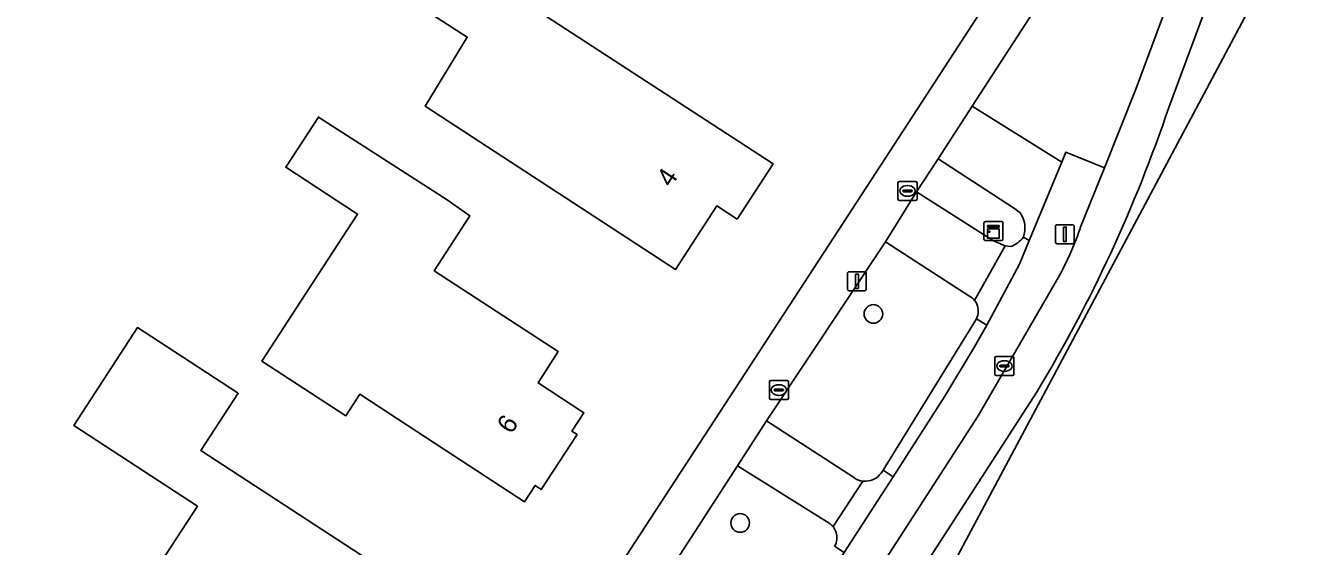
# Model space of a CAD drawing. Extents: x 161139 to 161601, y 381708 to 382245.
# Drawn here: x 161518.7 to 161586, y 382082.4 to 382109.7 of the extents above; entities that cross this region are included whole.
import ezdxf

# ---------------------------------------------------------------- set-up
doc = ezdxf.new("R2010")
doc.units = 0
for name, color, linetype in [('IMGEO_Boom', 7, 'Continuous'), ('IMGEO_Brandkraan', 7, 'Continuous'), ('IMGEO_Erf', 7, 'Continuous'), ('IMGEO_Groenvoorziening', 7, 'Continuous'), ('IMGEO_Kast', 7, 'Continuous'), ('IMGEO_Kolk', 7, 'Continuous'), ('IMGEO_Lichtmast', 7, 'Continuous'), ('IMGEO_Pand', 7, 'Continuous'), ('IMGEO_Pand_nummerreeks', 7, 'Continuous'), ('IMGEO_Parkeervlak_open', 7, 'Continuous'), ('IMGEO_Rijbaan_lokaal_gesloten', 7, 'Continuous'), ('IMGEO_Rijbaan_lokaal_open', 7, 'Continuous'), ('IMGEO_Voetpad_open', 7, 'Continuous')]:
    doc.layers.add(name, color=color, linetype=linetype)

msp = doc.modelspace()

# ---------------------------------------------------------------- linework, layer by layer
at = {"layer": 'IMGEO_Boom'}
for centre in [(161563.196, 382094.579), (161556.197, 382083.607)]:
    msp.add_circle(centre, 0.489, dxfattribs=at)
at = {"layer": 'IMGEO_Brandkraan'}
for p, q in [((161557.732, 382090.159), (161557.732, 382091.011)), ((161557.807, 382091.085), (161558.659, 382091.085)), ((161558.22, 382090.865), (161558.245, 382090.865)), ((161558.733, 382091.011), (161558.733, 382090.159)), ((161557.991, 382090.579), (161557.991, 382090.591)), ((161558.429, 382090.542), (161558.031, 382090.542)), ((161558.034, 382090.628), (161558.432, 382090.628)), ((161558.243, 382090.305), (161558.218, 382090.305)), ((161558.475, 382090.591), (161558.475, 382090.579)), ((161558.659, 382090.085), (161557.807, 382090.085))]:
    msp.add_line(p, q, dxfattribs=at)
for points in [[(161557.732, 382090.159), (161557.732, 382091.011)], [(161557.807, 382091.085), (161558.659, 382091.085)], [(161558.733, 382091.011), (161558.733, 382090.159)], [(161558.659, 382090.085), (161557.807, 382090.085)]]:
    msp.add_lwpolyline(points, dxfattribs=at)
for centre, radius, start, end in [((161557.809, 382091.009), 0.0765, 91.55205, 178.44795), ((161557.809, 382091.009), 0.0765, 91.55205, 178.44795), ((161558.657, 382091.009), 0.0765, 1.55205, 88.44795), ((161558.657, 382091.009), 0.0765, 1.55205, 88.44795), ((161557.809, 382090.161), 0.0765, 181.55205, 268.44795), ((161557.809, 382090.161), 0.0765, 181.55205, 268.44795), ((161558.031, 382090.588), 0.0403, 85.87752, 175.75265), ((161558.028, 382090.578), 0.0366, 178.93798, 274.71019), ((161558.432, 382090.585), 0.043, 264.86636, 352.45326), ((161558.436, 382090.59), 0.0386, 1.73085, 96.63898), ((161558.657, 382090.161), 0.0765, 271.55205, 358.44795), ((161558.657, 382090.161), 0.0765, 271.55205, 358.44795)]:
    msp.add_arc(centre, radius, start, end, dxfattribs=at)
for centre, major_axis, ratio, start_param, end_param in [((161558.219, 382090.585), (-0.387, 0.002), 0.722429, 4.712389, 7.853982), ((161558.244, 382090.585), (-0.39, 0.002), 0.717154, 1.570796, 4.712389)]:
    msp.add_ellipse(centre, major_axis=major_axis, ratio=ratio, start_param=start_param, end_param=end_param, dxfattribs=at)
at = {"layer": 'IMGEO_Erf'}
msp.add_lwpolyline([(161553.295, 382144.911), (161544.61, 382147.101), (161500, 382158.072), (161477.956, 382163.494), (161457.897, 382168.303), (161418.52, 382178.097), (161389.844, 382185.251), (161387.058, 382185.651), (161384.186, 382184.996), (161381.949, 382183.375), (161380.259, 382181.034), (161377.586, 382172.934), (161374.321, 382163.969), (161372.26, 382158.835), (161369.98, 382153.637), (161365.084, 382143.565), (161365.175, 382143.293), (161389.855, 382127.317), (161408.789, 382114.947), (161450.498, 382088.211), (161500, 382056.07), (161523.437, 382040.853), (161561.628, 382099.383), (161581.409, 382129.761)], dxfattribs=at)
for points in [[(161548.616, 382099.647), (161539.661, 382105.481), (161541.863, 382109.109), (161539.49, 382110.634), (161540.764, 382112.614), (161536.361, 382115.445), (161539.948, 382117.916), (161544.995, 382114.67), (161543.277, 382111.999), (161543.522, 382111.842), (161553.735, 382105.188), (161557.924, 382102.459), (161556.035, 382099.56), (161554.976, 382100.25), (161552.805, 382096.917)], [(161534.048, 382104.912), (161540.81, 382100.569), (161542.007, 382099.725), (161540.131, 382096.846), (161545.242, 382093.515), (161546.648, 382092.599), (161545.581, 382090.962), (161547.984, 382089.396), (161547.357, 382088.433), (161547.633, 382088.253), (161545.753, 382085.367), (161545.435, 382085.575), (161544.88, 382084.724), (161540.691, 382087.454), (161536.228, 382090.362), (161535.491, 382089.231), (161531.076, 382092.108), (161534.302, 382097.059), (161536.104, 382099.824), (161532.334, 382102.281)], [(161527.701, 382084.489), (161521.198, 382088.726), (161524.545, 382093.864), (161525.651, 382093.143), (161529.841, 382090.414), (161527.88, 382087.405), (161541.06, 382078.818), (161536.96, 382072.525), (161532.764, 382075.259), (161532.059, 382074.178), (161528.63, 382076.412), (161529.353, 382077.522), (161525.007, 382080.354)]]:
    msp.add_lwpolyline(points, close=True, dxfattribs=at)
at = {"layer": 'IMGEO_Groenvoorziening'}
msp.add_lwpolyline([(161579.832, 382114.053), (161581.47, 382118.537), (161583.268, 382124.041), (161581.267, 382125.334), (161568.38, 382105.476), (161573.086, 382102.543), (161573.302, 382103.064), (161575.329, 382102.253), (161576.98, 382106.377)], close=True, dxfattribs=at)
for points in [[(161566.592, 382102.722), (161565.463, 382100.982), (161569.51, 382098.421), (161570.115, 382098.159), (161570.416, 382098.113)], [(161570.897, 382099.892), (161570.551, 382100.153), (161566.592, 382102.722)], [(161568.212, 382095.532), (161563.831, 382098.367), (161557.579, 382088.971), (161562.195, 382085.975)], [(161563.596, 382086.216), (161563.702, 382086.387), (161568.611, 382094.325)], [(161560.731, 382083.685), (161556.061, 382086.613), (161549.678, 382076.751), (161554.422, 382073.613)], [(161562.648, 382085.805), (161562.819, 382085.798)]]:
    msp.add_lwpolyline(points, dxfattribs=at)
for centre, radius, start, end in [((161569.741, 382099.077), 1.414, 340.48835, 35.17308), ((161569.9, 382099.489), 1.469, 290.54939, 323.02303), ((161567.826, 382094.75), 0.872, 37.93195, 63.73762), ((161567.819, 382094.73), 0.89, 24.7571, 38.63242), ((161567.803, 382094.731), 0.904, 333.32683, 24.31686), ((161562.77, 382086.82), 1.023, 272.73451, 323.82302), ((161562.771, 382086.822), 1.025, 235.774, 263.0862), ((161560.341, 382082.836), 0.935, 38.2235, 65.31507), ((161560.326, 382082.82), 0.956, 17.67097, 38.43487), ((161560.344, 382082.836), 0.935, 330.87903, 17.06204)]:
    msp.add_arc(centre, radius, start, end, dxfattribs=at)
at = {"layer": 'IMGEO_Kast'}
for p, q in [((161569.001, 382098.502), (161569.001, 382099.343)), ((161569.001, 382099.343), (161569.001, 382098.502)), ((161569.076, 382099.427), (161569.917, 382099.427)), ((161569.917, 382099.427), (161569.076, 382099.427)), ((161570.001, 382099.352), (161570.001, 382098.511)), ((161570.001, 382098.511), (161570.001, 382099.352)), ((161569.926, 382098.427), (161569.085, 382098.427)), ((161569.085, 382098.427), (161569.926, 382098.427))]:
    msp.add_line(p, q, dxfattribs=at)
for points in [[(161569.196, 382099.217), (161569.796, 382099.217), (161569.796, 382099.132), (161569.196, 382099.132), (161569.196, 382099.217)], [(161569.196, 382099.042), (161569.796, 382099.042), (161569.796, 382098.553), (161569.196, 382098.553), (161569.196, 382099.042)]]:
    msp.add_lwpolyline(points, dxfattribs=at)
msp.add_circle((161569.28, 382098.891), 0.0377, dxfattribs=at)
for centre, start, end in [((161569.079, 382099.349), 92.4484, 184.28452), ((161569.079, 382099.349), 92.4484, 184.28452), ((161569.923, 382099.349), 2.4484, 94.28452), ((161569.923, 382099.349), 2.4484, 94.28452), ((161569.079, 382098.505), 182.4484, 274.28452), ((161569.079, 382098.505), 182.4484, 274.28452), ((161569.923, 382098.505), 272.4484, 4.28452), ((161569.923, 382098.505), 272.4484, 4.28452)]:
    msp.add_arc(centre, 0.0779, start, end, dxfattribs=at)
at = {"layer": 'IMGEO_Kolk'}
for p, q in [((161564.487, 382100.61), (161564.487, 382101.462)), ((161564.562, 382101.536), (161565.414, 382101.536)), ((161564.746, 382101.03), (161564.746, 382101.042)), ((161565.184, 382100.993), (161564.786, 382100.993)), ((161564.789, 382101.079), (161565.187, 382101.079)), ((161564.975, 382101.316), (161565, 382101.316)), ((161565.23, 382101.042), (161565.23, 382101.03)), ((161565.488, 382101.462), (161565.488, 382100.61)), ((161565.414, 382100.536), (161564.562, 382100.536)), ((161564.998, 382100.756), (161564.973, 382100.756)), ((161569.577, 382091.419), (161569.577, 382092.271)), ((161569.652, 382092.345), (161570.504, 382092.345)), ((161570.578, 382092.271), (161570.578, 382091.419)), ((161569.836, 382091.839), (161569.836, 382091.851)), ((161570.274, 382091.802), (161569.876, 382091.802)), ((161569.879, 382091.888), (161570.277, 382091.888)), ((161570.088, 382091.565), (161570.063, 382091.565)), ((161570.065, 382092.125), (161570.09, 382092.125)), ((161570.32, 382091.851), (161570.32, 382091.839)), ((161570.504, 382091.345), (161569.652, 382091.345))]:
    msp.add_line(p, q, dxfattribs=at)
for points in [[(161564.487, 382100.61), (161564.487, 382101.462)], [(161564.562, 382101.536), (161565.414, 382101.536)], [(161565.488, 382101.462), (161565.488, 382100.61)], [(161565.414, 382100.536), (161564.562, 382100.536)], [(161569.577, 382091.419), (161569.577, 382092.271)], [(161569.652, 382092.345), (161570.504, 382092.345)], [(161570.578, 382092.271), (161570.578, 382091.419)], [(161570.504, 382091.345), (161569.652, 382091.345)]]:
    msp.add_lwpolyline(points, dxfattribs=at)
for centre, radius, start, end in [((161564.564, 382101.46), 0.0765, 91.55205, 178.44795), ((161564.564, 382101.46), 0.0765, 91.55205, 178.44795), ((161564.786, 382101.039), 0.0403, 85.87752, 175.75265), ((161564.783, 382101.029), 0.0366, 178.93798, 274.71019), ((161565.187, 382101.036), 0.043, 264.86636, 352.45326), ((161565.191, 382101.041), 0.0386, 1.73085, 96.63898), ((161565.412, 382101.46), 0.0765, 1.55205, 88.44795), ((161565.412, 382101.46), 0.0765, 1.55205, 88.44795), ((161564.564, 382100.612), 0.0765, 181.55205, 268.44795), ((161564.564, 382100.612), 0.0765, 181.55205, 268.44795), ((161565.412, 382100.612), 0.0765, 271.55205, 358.44795), ((161565.412, 382100.612), 0.0765, 271.55205, 358.44795), ((161569.654, 382092.269), 0.0765, 91.55205, 178.44795), ((161569.654, 382092.269), 0.0765, 91.55205, 178.44795), ((161570.502, 382092.269), 0.0765, 1.55205, 88.44795), ((161570.502, 382092.269), 0.0765, 1.55205, 88.44795), ((161569.876, 382091.848), 0.0403, 85.87752, 175.75265), ((161569.873, 382091.838), 0.0366, 178.93798, 274.71019), ((161570.277, 382091.845), 0.043, 264.86636, 352.45326), ((161570.281, 382091.85), 0.0386, 1.73085, 96.63898), ((161569.654, 382091.421), 0.0765, 181.55205, 268.44795), ((161569.654, 382091.421), 0.0765, 181.55205, 268.44795), ((161570.502, 382091.421), 0.0765, 271.55205, 358.44795), ((161570.502, 382091.421), 0.0765, 271.55205, 358.44795)]:
    msp.add_arc(centre, radius, start, end, dxfattribs=at)
for centre, major_axis, ratio, start_param, end_param in [((161564.974, 382101.036), (-0.387, 0.002), 0.722429, 4.712389, 7.853982), ((161564.999, 382101.036), (-0.39, 0.002), 0.717154, 1.570796, 4.712389), ((161570.064, 382091.845), (-0.387, 0.002), 0.722429, 4.712389, 7.853982), ((161570.089, 382091.845), (-0.39, 0.002), 0.717154, 1.570796, 4.712389)]:
    msp.add_ellipse(centre, major_axis=major_axis, ratio=ratio, start_param=start_param, end_param=end_param, dxfattribs=at)
at = {"layer": 'IMGEO_Lichtmast'}
for p, q in [((161572.752, 382098.361), (161572.752, 382099.161)), ((161572.752, 382099.161), (161572.752, 382098.361)), ((161572.852, 382099.261), (161573.642, 382099.261)), ((161573.642, 382099.261), (161572.852, 382099.261)), ((161573.742, 382099.161), (161573.742, 382098.361)), ((161573.742, 382098.361), (161573.742, 382099.161)), ((161573.642, 382098.261), (161572.852, 382098.261)), ((161572.852, 382098.261), (161573.642, 382098.261)), ((161561.835, 382095.892), (161561.835, 382096.692)), ((161561.835, 382096.692), (161561.835, 382095.892)), ((161561.935, 382096.792), (161562.725, 382096.792)), ((161562.725, 382096.792), (161561.935, 382096.792)), ((161562.825, 382096.692), (161562.825, 382095.892)), ((161562.825, 382095.892), (161562.825, 382096.692)), ((161562.725, 382095.792), (161561.935, 382095.792)), ((161561.935, 382095.792), (161562.725, 382095.792))]:
    msp.add_line(p, q, dxfattribs=at)
for points in [[(161573.172, 382099.136), (161573.322, 382099.136), (161573.322, 382098.386), (161573.172, 382098.386), (161573.172, 382099.136)], [(161562.255, 382096.667), (161562.405, 382096.667), (161562.405, 382095.917), (161562.255, 382095.917), (161562.255, 382096.667)]]:
    msp.add_lwpolyline(points, dxfattribs=at)
for centre, start, end in [((161572.852, 382099.161), 90, 180), ((161572.852, 382099.161), 90, 180), ((161573.642, 382099.161), 0, 90), ((161573.642, 382099.161), 360, 90), ((161572.852, 382098.361), 180, 270), ((161572.852, 382098.361), 180, 270), ((161573.642, 382098.361), 270, 0), ((161573.642, 382098.361), 270, 0), ((161561.935, 382096.692), 90, 180), ((161561.935, 382096.692), 90, 180), ((161562.725, 382096.692), 0, 90), ((161562.725, 382096.692), 360, 90), ((161561.935, 382095.892), 180, 270), ((161561.935, 382095.892), 180, 270), ((161562.725, 382095.892), 270, 0), ((161562.725, 382095.892), 270, 0)]:
    msp.add_arc(centre, 0.1, start, end, dxfattribs=at)
at = {"layer": 'IMGEO_Pand'}
for points in [[(161548.616, 382099.647), (161552.805, 382096.917), (161554.976, 382100.25), (161556.035, 382099.56), (161557.924, 382102.459), (161553.735, 382105.188), (161543.522, 382111.842), (161543.277, 382111.999), (161544.995, 382114.67), (161539.948, 382117.916), (161536.361, 382115.445), (161540.764, 382112.614), (161539.49, 382110.634), (161541.863, 382109.109), (161539.661, 382105.481)], [(161542.007, 382099.725), (161540.81, 382100.569), (161534.048, 382104.912), (161532.334, 382102.281), (161536.104, 382099.824), (161534.302, 382097.059), (161531.076, 382092.108), (161535.491, 382089.231), (161536.228, 382090.362), (161540.691, 382087.454), (161544.88, 382084.724), (161545.435, 382085.575), (161545.753, 382085.367), (161547.633, 382088.253), (161547.357, 382088.433), (161547.984, 382089.396), (161545.581, 382090.962), (161546.648, 382092.599), (161545.242, 382093.515), (161540.131, 382096.846)], [(161525.007, 382080.354), (161529.353, 382077.522), (161528.63, 382076.412), (161532.059, 382074.178), (161532.764, 382075.259), (161536.96, 382072.525), (161541.06, 382078.818), (161527.88, 382087.405), (161529.841, 382090.414), (161525.651, 382093.143), (161524.545, 382093.864), (161521.198, 382088.726), (161527.701, 382084.489)]]:
    msp.add_lwpolyline(points, close=True, dxfattribs=at)
at = {"layer": 'IMGEO_Parkeervlak_open'}
for points in [[(161574.099, 382099.179), (161575.329, 382102.253), (161573.302, 382103.064), (161573.086, 382102.543), (161571.379, 382098.431), (161570.865, 382097.191), (161569.158, 382093.992), (161568.512, 382092.854), (161566.951, 382090.262), (161564.239, 382086.032), (161561.667, 382082.065), (161556.335, 382073.842), (161553.645, 382069.693), (161548.411, 382061.62), (161545.69, 382057.424), (161540.456, 382049.35), (161538.374, 382046.036), (161537.696, 382045.093), (161534.437, 382040.067), (161534.33, 382039.471), (161534.799, 382037.517)], [(161568.691, 382089.227), (161572.916, 382096.506)], [(161534.744, 382036.848), (161535.916, 382038.476), (161568.691, 382089.227)]]:
    msp.add_lwpolyline(points, dxfattribs=at)
msp.add_arc((161558.542, 382104.466), 16.43, 331.02362, 341.23052, dxfattribs=at)
at = {"layer": 'IMGEO_Rijbaan_lokaal_gesloten'}
for points in [[(161583.333, 382124.239), (161583.268, 382124.041), (161581.47, 382118.537), (161579.832, 382114.053), (161576.98, 382106.377), (161575.329, 382102.253), (161574.099, 382099.179)], [(161578.708, 382105.416), (161583.363, 382117.958), (161584.845, 382122.205)], [(161572.916, 382096.506), (161568.691, 382089.227), (161535.916, 382038.476), (161534.744, 382036.848), (161534.678, 382036.739), (161536.35, 382035.66), (161571.794, 382090.515)]]:
    msp.add_lwpolyline(points, dxfattribs=at)
for centre, radius, start, end in [((161507.44, 382129.429), 75.205, 328.83886, 341.37895), ((161558.542, 382104.466), 16.43, 331.02362, 341.23052)]:
    msp.add_arc(centre, radius, start, end, dxfattribs=at)
at = {"layer": 'IMGEO_Rijbaan_lokaal_open'}
for points in [[(161583.363, 382117.958), (161578.708, 382105.416)], [(161571.794, 382090.515), (161536.35, 382035.66), (161537.898, 382034.67), (161561.301, 382070.022), (161583.53, 382111.715), (161586.04, 382116.528)]]:
    msp.add_lwpolyline(points, dxfattribs=at)
msp.add_arc((161507.44, 382129.429), 75.205, 328.83886, 341.37895, dxfattribs=at)
at = {"layer": 'IMGEO_Voetpad_open'}
for points in [[(161581.409, 382129.761), (161561.628, 382099.383), (161523.437, 382040.853), (161525.518, 382039.495), (161528.456, 382043.995), (161532.291, 382049.829), (161533.813, 382052.367), (161540.355, 382062.295), (161541.805, 382064.505), (161548.238, 382074.428), (161549.678, 382076.751), (161556.061, 382086.613), (161557.579, 382088.971), (161563.831, 382098.367), (161565.463, 382100.982), (161566.592, 382102.722), (161568.38, 382105.476), (161581.267, 382125.334)], [(161568.38, 382105.476), (161566.592, 382102.722), (161570.551, 382100.153), (161570.897, 382099.892)], [(161571.074, 382098.605), (161571.379, 382098.431), (161573.086, 382102.543), (161568.38, 382105.476)], [(161569.51, 382098.421), (161565.463, 382100.982), (161563.831, 382098.367), (161568.212, 382095.532)], [(161568.514, 382095.286), (161570.115, 382098.159), (161569.51, 382098.421)], [(161570.865, 382097.191), (161571.379, 382098.431), (161571.074, 382098.605)], [(161570.416, 382098.113), (161570.115, 382098.159), (161568.514, 382095.286)], [(161568.611, 382094.325), (161569.158, 382093.992), (161570.865, 382097.191)], [(161557.579, 382088.971), (161556.061, 382086.613), (161560.731, 382083.685)], [(161562.195, 382085.975), (161557.579, 382088.971)], [(161564.239, 382086.032), (161563.702, 382086.387), (161563.596, 382086.216)], [(161562.819, 382085.798), (161562.648, 382085.805), (161561.075, 382083.414)], [(161561.075, 382083.414), (161562.648, 382085.805)], [(161561.16, 382082.381), (161561.667, 382082.065), (161564.239, 382086.032)]]:
    msp.add_lwpolyline(points, dxfattribs=at)
msp.add_lwpolyline([(161569.158, 382093.992), (161568.611, 382094.325), (161563.702, 382086.387), (161564.239, 382086.032), (161566.951, 382090.262), (161568.512, 382092.854)], close=True, dxfattribs=at)
for centre, radius, start, end in [((161569.741, 382099.077), 1.414, 340.48835, 35.17308), ((161569.9, 382099.489), 1.469, 290.54939, 323.02303), ((161567.826, 382094.75), 0.872, 37.93195, 63.73762), ((161567.819, 382094.73), 0.89, 24.7571, 38.63242), ((161567.803, 382094.731), 0.904, 333.32683, 24.31686), ((161562.77, 382086.82), 1.023, 272.73451, 323.82302), ((161562.771, 382086.822), 1.025, 235.774, 263.0862), ((161560.341, 382082.836), 0.935, 38.2235, 65.31507), ((161560.326, 382082.82), 0.956, 17.67097, 38.43487), ((161560.344, 382082.836), 0.935, 330.87903, 17.06204)]:
    msp.add_arc(centre, radius, start, end, dxfattribs=at)

# ---------------------------------------------------------------- texts
at = {"layer": 'IMGEO_Pand_nummerreeks'}
for s, rotation, p in [('4', 56.92118, (161552.573, 382101.177)), ('6', 56.40059, (161544.181, 382088.225))]:
    msp.add_text(s, height=1, rotation=rotation, dxfattribs=at).set_placement(p)

doc.saveas('drawing.dxf')
